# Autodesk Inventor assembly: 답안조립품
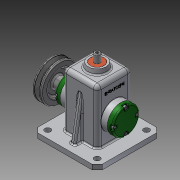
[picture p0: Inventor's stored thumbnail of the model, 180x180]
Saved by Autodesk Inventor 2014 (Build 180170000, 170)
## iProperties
Created: 2016-02
Part Number: 답안조립품
Document SubType Name: Assembly
Designer: G.C.Oh
Author: G.C.Oh
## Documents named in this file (16)
- C:\Users\Administrator\Desktop\460211V1034\답안조립품.iam
- C:\Users\Administrator\Desktop\460211V1034\1-본체.ipt
- C:\Users\Administrator\Desktop\460211V1034\V벨트풀리.ipt
- C:\Users\Administrator\Desktop\460211V1034\고정핀 1.2 x 10.ipt
- C:\Users\Administrator\Desktop\460211V1034\뒤커버.ipt
- C:\Users\Administrator\Desktop\460211V1034\링크.ipt
- C:\Users\Administrator\Desktop\460211V1034\멈춤나사 M3x8.ipt
- C:\Users\Administrator\Desktop\460211V1034\베어링 12 x 32 x 10.ipt
- C:\Users\Administrator\Desktop\460211V1034\볼트 M4 x 12.ipt
- C:\Users\Administrator\Desktop\460211V1034\부시.ipt
- C:\Users\Administrator\Desktop\460211V1034\슬라이드.ipt
- C:\Users\Administrator\Desktop\460211V1034\앞커버.ipt
- C:\Users\Administrator\Desktop\460211V1034\오일실 12 25 7.ipt
- C:\Users\Administrator\Desktop\460211V1034\키 4 x 4 x 10.ipt
- C:\Users\Administrator\Desktop\460211V1034\편심축.ipt
- C:\Users\Administrator\Desktop\460211V1034\핀 5 x 18.ipt
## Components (12 placed, 5 different names)
1. 1-본체:1 — 각도:1, 각도:2
2. V벨트풀리:1 — 각도:4
3. 고정핀 1.2 x 10:1 — 각도:5
4. 핀 5 x 18:1
5. ISO 4762 M4 x 12:2 — 각도:1
6. ISO 4762 M4 x 12:3
7. ISO 4762 M4 x 12:4
8. ISO 4762 M4 x 12:5
9. ISO 4762 M4 x 12:1 — 각도:2
10. ISO 4762 M4 x 12:6
11. ISO 4762 M4 x 12:7
12. ISO 4762 M4 x 12:8
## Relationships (4: Angle 4)
- 각도:1 [Angle]: 1-본체:1 ↔ ISO 4762 M4 x 12:2
- 각도:2 [Angle]: 1-본체:1 ↔ ISO 4762 M4 x 12:1
- 각도:4 [Angle]: V벨트풀리:1
- 각도:5 [Angle]: 고정핀 1.2 x 10:1
